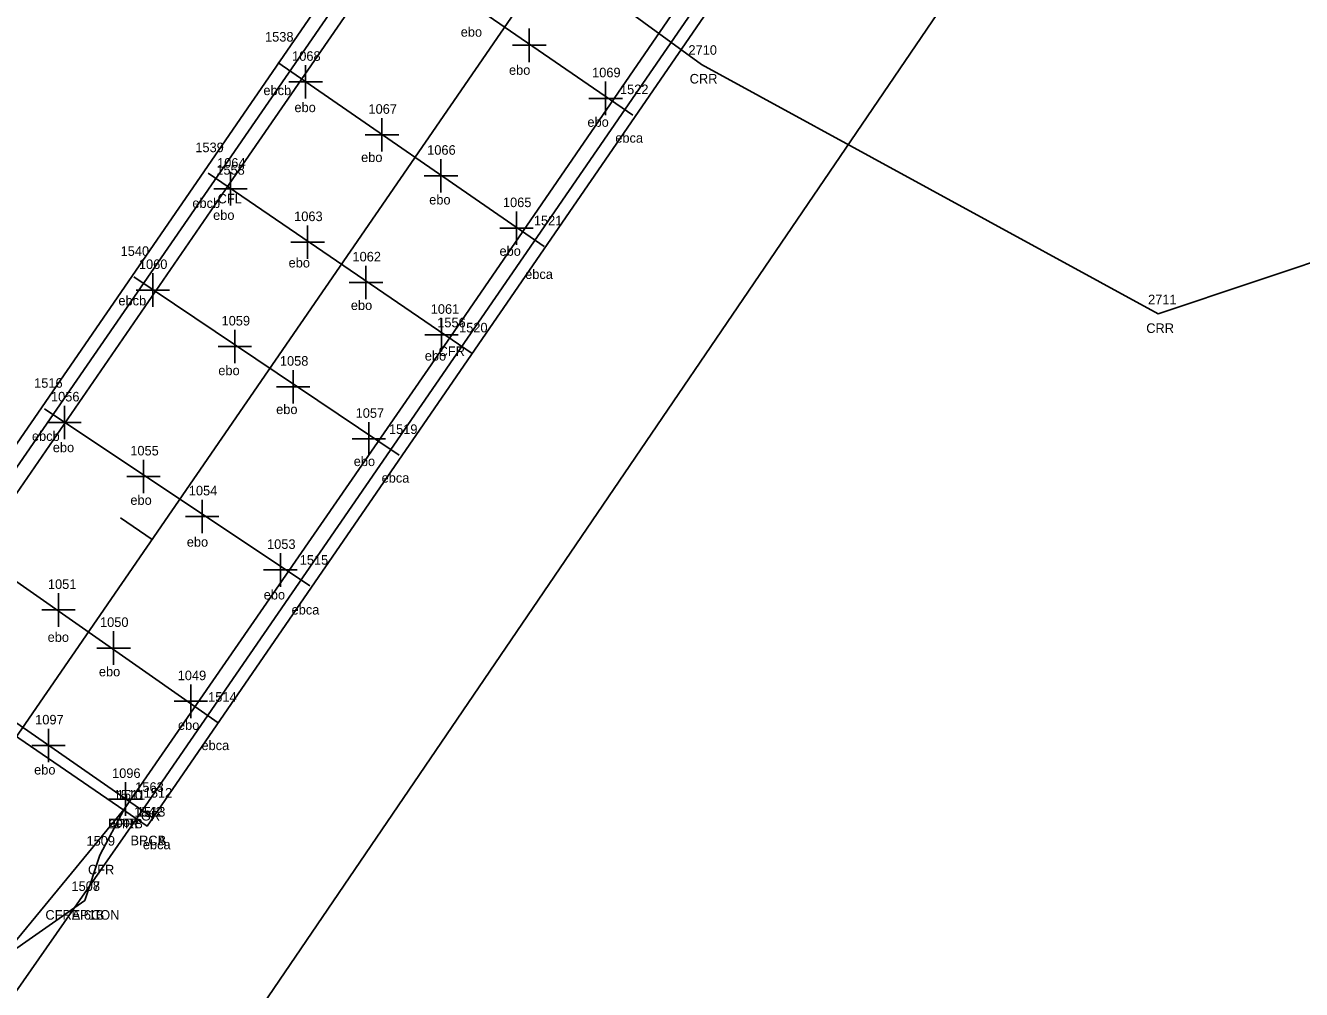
# Model space of a CAD drawing. Extents: x 2266664 to 2272542, y 716533 to 724777.
# Drawn here: x 2267567.2 to 2267700.4, y 717769.3 to 717870 of the extents above; entities that cross this region are included whole.
import ezdxf

# ---------------------------------------------------------------- set-up
doc = ezdxf.new("R2010")
doc.units = 0
for name, color, linetype in [('RD_EX_Bridge', 7, 'Continuous'), ('RD_EX_Bridge_txCode', 7, 'Continuous'), ('RD_EX_Conc', 7, 'Continuous'), ('RD_EX_Conc_txCode', 7, 'Continuous'), ('RD_EX_GuardRail', 7, 'Continuous'), ('RD_EX_GuardRail_txCode', 7, 'Continuous'), ('RD_EX_H2O', 7, 'Continuous'), ('RD_EX_H2O_txCode', 7, 'Continuous'), ('RD_EX_Misc', 7, 'Continuous'), ('RD_EX_Misc_txCode', 7, 'Continuous'), ('RD_EX_Road', 7, 'Continuous'), ('RD_EX_Road_txCode', 7, 'Continuous'), ('RD_EX_VEG', 7, 'Continuous'), ('RD_HC_Cl', 7, 'Continuous'), ('RD_HC_Data_Tic', 7, 'Continuous'), ('RD_SMD_Locator', 7, 'Continuous')]:
    doc.layers.add(name, color=color, linetype=linetype)

msp = doc.modelspace()

# ---------------------------------------------------------------- linework, layer by layer
at = {"layer": 'RD_EX_Bridge'}
msp.add_lwpolyline([(2267579.87, 717786.35), (2267681.7, 717934.49), (2267653.9, 717953.76), (2267551.93, 717805.48), (2267579.87, 717786.35)], dxfattribs=at)
at = {"layer": 'RD_EX_Conc'}
for points in [[(2267554.32, 717803.83), (2267588.43, 717853.38), (2267622.37, 717902.6), (2267656.38, 717951.92), (2267659.04, 717957.15), (2267660.25, 717961.55)], [(2267573.36, 717778.58), (2267574.92, 717783.31), (2267577.48, 717788.12), (2267611.53, 717837.44), (2267645.35, 717886.7), (2267679.35, 717936.13)]]:
    msp.add_lwpolyline(points, dxfattribs=at)
at = {"layer": 'RD_EX_GuardRail'}
for points in [[(2267481.72, 717701.57), (2267534.2, 717777.68), (2267554.26, 717806.46), (2267653.96, 717951.11), (2267712.38, 718036.08), (2267729.57, 718061.3)], [(2267506.03, 717677.39), (2267559.71, 717759.86), (2267580, 717788.93), (2267679.56, 717933.57), (2267740.09, 718016.9), (2267757.63, 718042.07)]]:
    msp.add_lwpolyline(points, dxfattribs=at)
at = {"layer": 'RD_EX_H2O'}
msp.add_lwpolyline([(2267591.63, 717899.51), (2267637.77, 717865.9), (2267685.44, 717839.85), (2267756.83, 717863.74), (2267826.13, 717888.16), (2267866.36, 717887.16), (2267930.84, 717899.12), (2268026.36, 717789.97), (2268079.49, 717725.08)], dxfattribs=at)
at = {"layer": 'RD_EX_Misc'}
for p, q in [((2267630.59, 717860.59), (2267603.04, 717879.53)), ((2267619.77, 717869.64), (2267619.77, 717866.14)), ((2267621.52, 717867.89), (2267618.02, 717867.89)), ((2267621.31, 717846.89), (2267593.53, 717866.08)), ((2267596.42, 717865.82), (2267596.42, 717862.32)), ((2267598.17, 717864.07), (2267594.67, 717864.07)), ((2267627.74, 717864.1), (2267627.74, 717860.6)), ((2267629.49, 717862.35), (2267625.99, 717862.35)), ((2267604.39, 717860.29), (2267604.39, 717856.79)), ((2267606.14, 717858.54), (2267602.64, 717858.54)), ((2267610.55, 717856.01), (2267610.55, 717852.51)), ((2267613.82, 717835.71), (2267586.24, 717854.53)), ((2267588.58, 717854.66), (2267588.58, 717851.16)), ((2267612.3, 717854.26), (2267608.8, 717854.26)), ((2267590.33, 717852.91), (2267586.83, 717852.91)), ((2267618.43, 717850.54), (2267618.43, 717847.04)), ((2267596.63, 717849.08), (2267596.63, 717845.58)), ((2267620.18, 717848.79), (2267616.68, 717848.79)), ((2267598.38, 717847.33), (2267594.88, 717847.33)), ((2267580.46, 717844.08), (2267580.46, 717840.58)), ((2267602.72, 717844.87), (2267602.72, 717841.37)), ((2267606.18, 717825.1), (2267578.48, 717843.7)), ((2267604.47, 717843.12), (2267600.97, 717843.12)), ((2267582.21, 717842.33), (2267578.71, 717842.33)), ((2267610.61, 717839.4), (2267610.61, 717835.9)), ((2267589.03, 717838.18), (2267589.03, 717834.68)), ((2267612.36, 717837.65), (2267608.86, 717837.65)), ((2267590.78, 717836.43), (2267587.28, 717836.43)), ((2267595.12, 717833.98), (2267595.12, 717830.48)), ((2267596.87, 717832.23), (2267593.37, 717832.23)), ((2267596.86, 717811.45), (2267569.15, 717829.93)), ((2267571.24, 717830.25), (2267571.24, 717826.75)), ((2267572.99, 717828.5), (2267569.49, 717828.5)), ((2267603.02, 717828.54), (2267603.02, 717825.04)), ((2267604.77, 717826.79), (2267601.27, 717826.79)), ((2267579.49, 717824.61), (2267579.49, 717821.11)), ((2267581.24, 717822.86), (2267577.74, 717822.86)), ((2267585.61, 717820.44), (2267585.61, 717816.94)), ((2267587.36, 717818.69), (2267583.86, 717818.69)), ((2267587.3, 717797.14), (2267559.79, 717816.37)), ((2267593.78, 717814.85), (2267593.78, 717811.35)), ((2267595.53, 717813.1), (2267592.03, 717813.1)), ((2267570.61, 717810.67), (2267570.61, 717807.17)), ((2267572.36, 717808.92), (2267568.86, 717808.92)), ((2267580.57, 717787.13), (2267552.28, 717806.79)), ((2267576.37, 717806.7), (2267576.37, 717803.2)), ((2267578.12, 717804.95), (2267574.62, 717804.95)), ((2267584.44, 717801.14), (2267584.44, 717797.64)), ((2267586.19, 717799.39), (2267582.69, 717799.39)), ((2267569.57, 717796.52), (2267569.57, 717793.02)), ((2267571.32, 717794.77), (2267567.82, 717794.77)), ((2267577.62, 717790.93), (2267577.62, 717787.43)), ((2267579.37, 717789.18), (2267575.87, 717789.18))]:
    msp.add_line(p, q, dxfattribs=at)
at = {"layer": 'RD_EX_Road'}
msp.add_line((2267564.52, 717772.38), (2267573.36, 717778.58), dxfattribs=at)
msp.add_lwpolyline([(2266711.74, 716543.52), (2266760.73, 716613.35), (2266803.96, 716675.22), (2266852.26, 716745.1), (2266861.92, 716758.86), (2266897.35, 716809.34), (2266928.06, 716853.39), (2266979.23, 716926.79), (2267038.74, 717012.27), (2267098.79, 717098.14), (2267123.37, 717133.16), (2267147.47, 717167.75), (2267157.72, 717182.87), (2267214.02, 717263.41), (2267271.17, 717346.91), (2267311.09, 717404.37), (2267330.38, 717431.8), (2267384.12, 717510.57), (2267443.22, 717595.38), (2267501.41, 717680.42), (2267557.41, 717761.62), (2267564.52, 717772.38), (2267577.48, 717788.12)], dxfattribs=at)
at = {"layer": 'RD_EX_VEG'}
msp.add_lwpolyline([(2267330.42, 717346.12), (2267314.92, 717369.68), (2267464.99, 717583.46), (2267551.97, 717708.99), (2267721.53, 717958.13), (2267810.77, 718081.35), (2267867.02, 718039.18)], dxfattribs=at)
at = {"layer": 'RD_HC_Cl'}
msp.add_line((2267342.91, 717471.2), (2272360.46, 724762.59), dxfattribs=at)
at = {"layer": 'RD_HC_Data_Tic'}
msp.add_line((2267580.38, 717816.28), (2267577.08, 717818.54), dxfattribs=at)
at = {"layer": 'RD_SMD_Locator'}
for centre in [(2267637.77, 717865.9), (2267588.43, 717853.38), (2267685.44, 717839.85), (2267611.53, 717837.44), (2267577.48, 717788.12), (2267577.48, 717788.12), (2267580, 717788.93), (2267579.87, 717786.35), (2267579.87, 717786.35), (2267574.92, 717783.31), (2267573.36, 717778.58), (2267573.36, 717778.58)]:
    msp.add_circle(centre, 0.001, dxfattribs=at)

# ---------------------------------------------------------------- texts
at = {"layer": 'RD_EX_Bridge_txCode'}
for s, p in [('1542', (2267578.52, 717787.35)), ('1513', (2267578.8, 717787.35)), ('BRCA', (2267578.13, 717784.35)), ('BRCB', (2267578.14, 717784.35))]:
    msp.add_text(s, height=1, dxfattribs=at).set_placement(p)
at = {"layer": 'RD_EX_Conc_txCode'}
for s, p in [('1558', (2267587.09, 717854.38)), ('CFL', (2267587.23, 717851.38)), ('1556', (2267610.16, 717838.44)), ('CFR', (2267610.3, 717835.44)), ('1510', (2267576.38, 717789.12)), ('CFR', (2267576.26, 717786.12)), ('1509', (2267573.54, 717784.31)), ('CFR', (2267573.69, 717781.31)), ('1508', (2267571.97, 717779.58)), ('CFRA 6CON', (2267569.25, 717776.58))]:
    msp.add_text(s, height=1, dxfattribs=at).set_placement(p)
at = {"layer": 'RD_EX_GuardRail_txCode'}
for s, p in [('1563', (2267578.63, 717789.93)), ('GR', (2267579.22, 717786.93))]:
    msp.add_text(s, height=1, dxfattribs=at).set_placement(p)
at = {"layer": 'RD_EX_H2O_txCode'}
for s, p in [('2710', (2267636.39, 717866.9)), ('CRR', (2267636.52, 717863.9)), ('2711', (2267684.38, 717840.85)), ('CRR', (2267684.19, 717837.85))]:
    msp.add_text(s, height=1, dxfattribs=at).set_placement(p)
at = {"layer": 'RD_EX_Misc_txCode'}
for s, p in [('1538', (2267592.18, 717868.28)), ('ebo', (2267612.61, 717868.79)), ('1068', (2267595.01, 717866.27)), ('ebo', (2267617.65, 717864.81)), ('1069', (2267626.33, 717864.55)), ('ebcb', (2267592.01, 717862.69)), ('1522', (2267629.24, 717862.79)), ('ebo', (2267595.25, 717860.91)), ('1067', (2267602.98, 717860.74)), ('ebo', (2267625.84, 717859.38)), ('ebca', (2267628.75, 717857.72)), ('1539', (2267584.9, 717856.73)), ('1066', (2267609.11, 717856.46)), ('1064', (2267587.17, 717855.11)), ('ebo', (2267602.21, 717855.7)), ('ebcb', (2267584.59, 717850.91)), ('ebo', (2267609.32, 717851.27)), ('1065', (2267617.02, 717850.99)), ('ebo', (2267586.76, 717849.66)), ('1063', (2267595.22, 717849.53)), ('1521', (2267620.25, 717849.09)), ('1540', (2267577.1, 717845.9)), ('ebo', (2267616.66, 717845.91)), ('1060', (2267579.01, 717844.53)), ('ebo', (2267594.64, 717844.69)), ('1062', (2267601.31, 717845.32)), ('ebca', (2267619.34, 717843.49)), ('ebcb', (2267576.87, 717840.73)), ('ebo', (2267601.14, 717840.25)), ('1061', (2267609.48, 717839.85)), ('1059', (2267587.64, 717838.63)), ('1520', (2267612.44, 717837.91)), ('ebo', (2267608.86, 717834.97)), ('1058', (2267593.73, 717834.43)), ('ebo', (2267587.3, 717833.44)), ('1516', (2267568.07, 717832.13)), ('1056', (2267569.83, 717830.7)), ('ebo', (2267593.34, 717829.38)), ('1057', (2267601.64, 717828.99)), ('1519', (2267605.12, 717827.3)), ('ebcb', (2267567.84, 717826.58)), ('ebo', (2267570.02, 717825.4)), ('1055', (2267578.11, 717825.06)), ('ebo', (2267601.44, 717823.95)), ('ebca', (2267604.35, 717822.22)), ('1054', (2267584.22, 717820.89)), ('ebo', (2267578.12, 717819.9)), ('ebo', (2267584.01, 717815.53)), ('1053', (2267592.39, 717815.3)), ('1515', (2267595.8, 717813.65)), ('1051', (2267569.51, 717811.12)), ('ebo', (2267592.04, 717810.02)), ('ebca', (2267594.95, 717808.45)), ('1050', (2267574.95, 717807.15)), ('ebo', (2267569.48, 717805.59)), ('ebo', (2267574.83, 717801.99)), ('1049', (2267583.06, 717801.59)), ('1514', (2267586.24, 717799.34)), ('1097', (2267568.18, 717796.97)), ('ebo', (2267583.09, 717796.4)), ('ebca', (2267585.54, 717794.29)), ('ebo', (2267568.07, 717791.74)), ('1096', (2267576.21, 717791.38)), ('1512', (2267579.51, 717789.33)), ('ebo', (2267575.85, 717786.27)), ('ebca', (2267579.42, 717783.93))]:
    msp.add_text(s, height=1, dxfattribs=at).set_placement(p)
at = {"layer": 'RD_EX_Road_txCode'}
for s, p in [('1511', (2267576.7, 717789.12)), ('EPRB', (2267575.78, 717786.12)), ('1507', (2267571.97, 717779.58)), ('EP1B', (2267571.97, 717776.58))]:
    msp.add_text(s, height=1, dxfattribs=at).set_placement(p)

doc.saveas('drawing.dxf')
